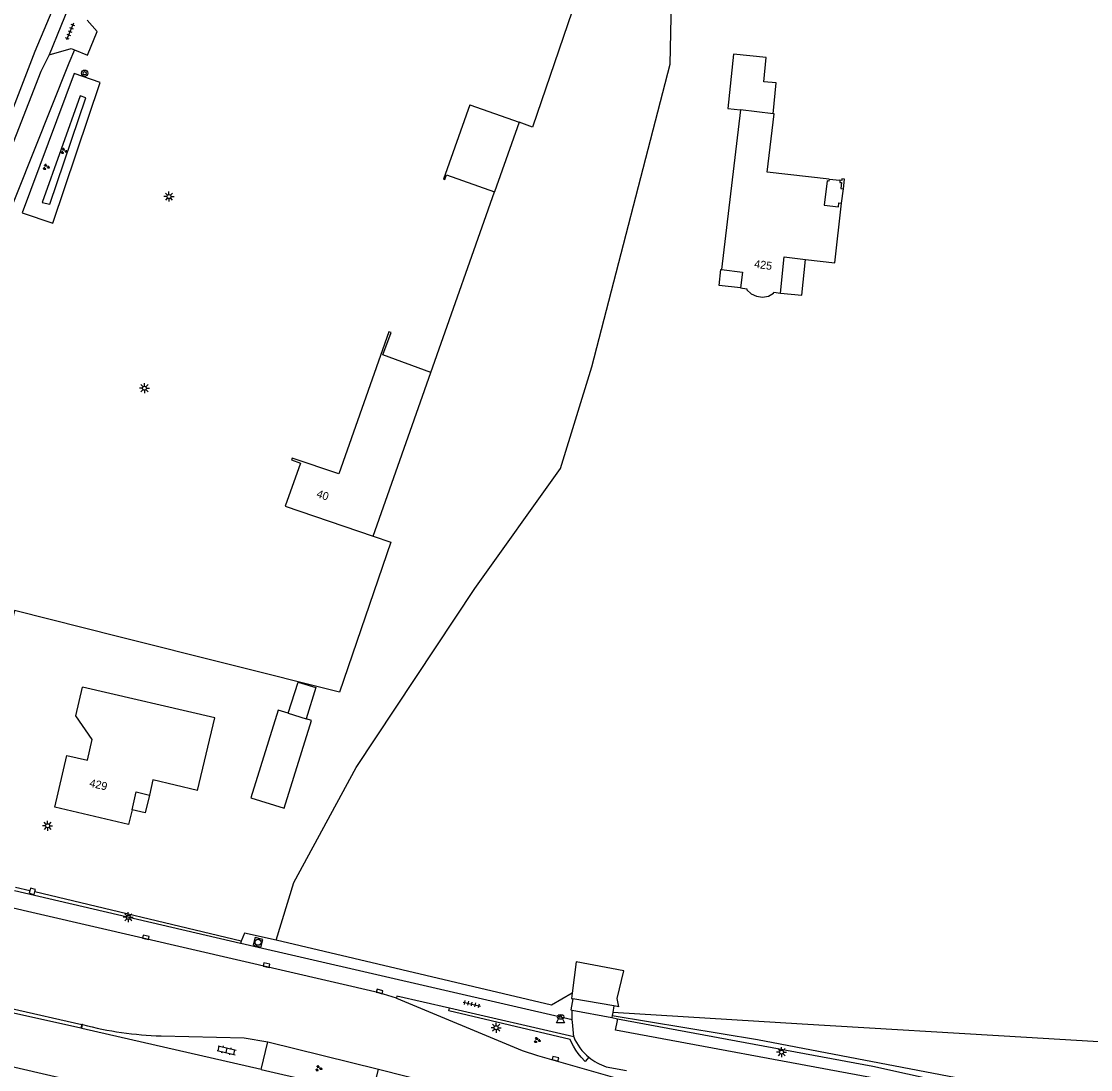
# Model space of a CAD drawing. Extents: x 128999 to 131010, y 395498 to 399007.
# Drawn here: x 130761.9 to 130895.4, y 396690 to 396821 of the extents above; entities that cross this region are included whole.
import ezdxf

# ---------------------------------------------------------------- set-up
doc = ezdxf.new("R2010")
doc.units = 0
for name, color, linetype in [('gg-afsc-hekwerk', 7, 'Continuous'), ('gg-afsc-muur', 7, 'Continuous'), ('gg-anno-huisnummerreeks BGT', 7, 'Continuous'), ('gg-bbg-bijgebouw', 7, 'Continuous'), ('gg-bbg-gedigitaliseerde bebouwing', 7, 'Continuous'), ('gg-bbg-gedigitaliseerde bijgebouw', 7, 'Continuous'), ('gg-bbg-hoofdgebouw', 7, 'Continuous'), ('gg-bbg-luifel en loopbrug', 7, 'Continuous'), ('gg-bbg-onder overbouw', 7, 'Continuous'), ('gg-bbg-pand overbouw', 7, 'Continuous'), ('gg-bbg-pilaar onder overbouw', 7, 'Continuous'), ('gg-bbg-pilaar pand', 7, 'Continuous'), ('gg-knt-BGT kruinlijn', 7, 'Continuous'), ('gg-knt-bovenkant onderkant talud', 7, 'Continuous'), ('gg-knt-verharding', 7, 'Continuous'), ('gg-knt-verharding nz', 7, 'Continuous'), ('gt-grn-groengrens', 7, 'Continuous'), ('gt-grn-weggrens', 7, 'Continuous'), ('gt-symb-boom', 7, 'Continuous'), ('gt-symb-brandkraan', 7, 'Continuous'), ('gt-symb-groenvak', 7, 'Continuous'), ('gt-symb-klinker verharding', 7, 'Continuous'), ('gt-symb-kolk', 7, 'Continuous'), ('gt-symb-lichtmast', 7, 'Continuous'), ('gt-symb-rioolschacht', 7, 'Continuous'), ('gt-symb-tegel verharding', 7, 'Continuous'), ('gt-symb-waterafsluiter', 7, 'Continuous')]:
    doc.layers.add(name, color=color, linetype=linetype)

# ---------------------------------------------------------------- blocks, each defined once
blk = doc.blocks.new('gt0-GRVAK')
at = {"layer": 'gt-symb-groenvak'}
for p, q in [((-0.11, 0.19), (-0.23, 0.24)), ((-0.18, 0.15), (0.09, 0.15)), ((-0.09, 0.21), (-0.16, 0.32)), ((-0.05, 0.21), (-0.05, 0.39)), ((0, 0.21), (0.06, 0.32)), ((0.01, 0.19), (0.13, 0.24)), ((0.26, -0.05), (0.2, 0.06)), ((0.31, -0.05), (0.31, 0.13)), ((0.35, -0.05), (0.41, 0.06)), ((-0.24, -0.23), (-0.36, -0.18)), ((-0.32, -0.26), (-0.05, -0.26)), ((-0.23, -0.21), (-0.29, -0.1)), ((-0.18, -0.2), (-0.18, -0.02)), ((-0.14, -0.21), (-0.07, -0.1)), ((-0.12, -0.23), (0, -0.18)), ((0.24, -0.07), (0.12, -0.02)), ((0.17, -0.11), (0.44, -0.11)), ((0.37, -0.07), (0.49, -0.02))]:
    blk.add_line(p, q, dxfattribs=at)
blk = doc.blocks.new('gt0-LMAST')
at = {"layer": 'gt-symb-lichtmast'}
for p, q in [((-0.18, 0.17), (-0.45, 0.44)), ((-0.01, 0.25), (-0.01, 0.62)), ((0.17, 0.17), (0.44, 0.44)), ((-0.26, 0), (-0.63, 0)), ((-0.18, -0.18), (-0.45, -0.45)), ((-0.01, -0.25), (-0.01, -0.63)), ((0.44, -0.45), (0.17, -0.18)), ((0.24, 0), (0.62, 0))]:
    blk.add_line(p, q, dxfattribs=at)
blk.add_circle((-0.01, 0), 0.25, dxfattribs=at)
blk = doc.blocks.new('gt0-KOLK')
at = {"layer": 'gt-symb-kolk'}
blk.add_lwpolyline([(0, 0), (0.38, 0), (0.38, 0.4), (-0.38, 0.4), (-0.38, 0), (0, 0)], dxfattribs=at)
blk = doc.blocks.new('gt0-RS')
at = {"layer": 'gt-symb-rioolschacht'}
blk.add_lwpolyline([(-0.5, -0.5), (0.5, -0.5), (0.5, 0.5), (-0.5, 0.5)], close=True, dxfattribs=at)
blk.add_circle((0, 0), 0.375, dxfattribs=at)
blk = doc.blocks.new('gt0-TEG1')
at = {"layer": 'gt-symb-tegel verharding'}
for p, q in [((-1.12, 0), (1.12, 0)), ((-0.9, -0.25), (-0.9, 0.25)), ((-0.45, -0.25), (-0.45, 0.25)), ((0, -0.25), (0, 0.25)), ((0.45, -0.25), (0.45, 0.25)), ((0.9, -0.25), (0.9, 0.25))]:
    blk.add_line(p, q, dxfattribs=at)
blk = doc.blocks.new('gt0-WAFSL')
at = {"layer": 'gt-symb-waterafsluiter'}
for p, q in [((-0.5, -0.33), (0, 0.67)), ((0, 0.67), (0.5, -0.33)), ((0.5, -0.33), (-0.5, -0.33))]:
    blk.add_line(p, q, dxfattribs=at)
blk = doc.blocks.new('gt0-BR')
at = {"layer": 'gt-symb-brandkraan'}
for centre, radius, start, end in [((-0.24, 0), 0.206, 107.5669, 252.4331), ((0.6, -2.66), 3, 106.892, 107.5669), ((0, -0.69), 0.938, 73.108, 106.892), ((-0.6, -2.66), 3, 72.4331, 73.108), ((0.24, 0), 0.206, 287.567, 72.4331), ((0.6, 2.66), 3, 252.4331, 253.108), ((0, 0.69), 0.938, 253.108, 286.8921), ((-0.6, 2.66), 3, 286.8921, 287.567)]:
    blk.add_arc(centre, radius, start, end, dxfattribs=at)
blk = doc.blocks.new('gt0-BOOM')
at = {"layer": 'gt-symb-boom'}
for radius in [0.4, 0.2]:
    blk.add_circle((0, 0), radius, dxfattribs=at)
blk = doc.blocks.new('gt0-KL1')
at = {"layer": 'gt-symb-klinker verharding'}
for p, q in [((-1.15, 0.3), (1.15, 0.3)), ((-1, -0.3), (-1, 0.3)), ((-0.5, 0.3), (-0.5, 0.45)), ((0, -0.3), (0, 0.3)), ((0.5, 0.3), (0.5, 0.45)), ((1, -0.3), (1, 0.3)), ((-1.15, -0.3), (1.15, -0.3)), ((-0.5, -0.45), (-0.5, -0.3)), ((0.5, -0.45), (0.5, -0.3))]:
    blk.add_line(p, q, dxfattribs=at)

msp = doc.modelspace()

# ---------------------------------------------------------------- linework, layer by layer
at = {"layer": 'gg-afsc-hekwerk'}
for p, q in [((130762.91, 396712.35), (130761.12, 396712.78)), ((130789.32, 396706.07), (130763.55, 396712.2))]:
    msp.add_line(p, q, dxfattribs=at)
for points in [[(130774.03, 396744.08), (130761, 396747.35), (130757.38, 396731.79)], [(130793.68, 396706.16), (130789.73, 396707.07), (130789.32, 396706.07)], [(130830.68, 396699.56), (130828.1, 396698.06), (130793.68, 396706.16)], [(130836.48, 396697.86), (130836.3, 396698.91), (130837.14, 396702.36), (130831.18, 396703.48), (130830.68, 396699.56)]]:
    msp.add_lwpolyline(points, dxfattribs=at)
at = {"layer": 'gg-afsc-muur'}
msp.add_line((130813.02, 396777.12), (130820.95, 396799.68), dxfattribs=at)
for points in [[(130762.91, 396712.35), (130762.84, 396712.04), (130763.48, 396711.89), (130763.55, 396712.2)], [(130763.55, 396712.2), (130763.62, 396712.52), (130762.99, 396712.66), (130762.91, 396712.35)]]:
    msp.add_lwpolyline(points, dxfattribs=at)
at = {"layer": 'gg-bbg-bijgebouw'}
msp.add_lwpolyline([(130817.88, 396810.55), (130814.61, 396801.25), (130814.74, 396801.2), (130814.95, 396801.79), (130820.95, 396799.68)], dxfattribs=at)
at = {"layer": 'gg-bbg-gedigitaliseerde bebouwing'}
for p, q in [((130805.82, 396756.65), (130813.02, 396777.12)), ((130794.83, 396760.41), (130805.82, 396756.65))]:
    msp.add_line(p, q, dxfattribs=at)
msp.add_lwpolyline([(130783.87, 396724.88), (130786.01, 396733.94), (130769.49, 396737.79)], dxfattribs=at)
at = {"layer": 'gg-bbg-gedigitaliseerde bijgebouw'}
for p, q in [((130817.88, 396810.55), (130824.04, 396808.36)), ((130824.04, 396808.36), (130820.95, 396799.68)), ((130795.2, 396734.53), (130797.44, 396733.83))]:
    msp.add_line(p, q, dxfattribs=at)
msp.add_lwpolyline([(130795.2, 396734.53), (130796.42, 396738.43), (130798.66, 396737.73), (130797.44, 396733.83)], dxfattribs=at)
at = {"layer": 'gg-bbg-hoofdgebouw'}
for p, q in [((130851.71, 396809.9), (130849.31, 396789.95)), ((130855.77, 396809.42), (130851.71, 396809.9))]:
    msp.add_line(p, q, dxfattribs=at)
for points in [[(130862.77, 396801.27), (130855.02, 396802.13), (130855.89, 396809.4), (130855.77, 396809.42)], [(130859.83, 396791.23), (130863.46, 396790.8), (130864.3, 396798.26)], [(130856.68, 396787.03), (130857.14, 396791.54), (130859.83, 396791.23)], [(130849.31, 396789.95), (130851.93, 396789.63), (130851.7, 396787.68)], [(130851.7, 396787.68), (130852.49, 396787.57), (130852.48, 396787.43), (130853.04, 396786.94), (130853.71, 396786.62), (130854.44, 396786.52), (130855.18, 396786.63), (130855.82, 396787.02), (130855.84, 396787.14), (130856.68, 396787.03)], [(130813.02, 396777.12), (130807.03, 396779.3), (130808.05, 396782.09), (130807.77, 396782.19), (130801.53, 396764.42), (130795.68, 396766.38), (130795.61, 396766.18), (130796.72, 396765.79), (130794.83, 396760.41)], [(130775.69, 396722.46), (130775.25, 396720.61), (130766.06, 396722.78), (130767.54, 396729.26), (130770.11, 396728.68), (130770.71, 396731.26), (130768.67, 396734.19), (130769.49, 396737.79)], [(130783.87, 396724.88), (130778.3, 396726.19), (130777.85, 396724.31)]]:
    msp.add_lwpolyline(points, dxfattribs=at)
at = {"layer": 'gg-bbg-luifel en loopbrug'}
for points in [[(130855.77, 396809.42), (130856.17, 396813.27), (130854.6, 396813.43), (130854.9, 396816.44), (130850.81, 396816.86), (130850.11, 396810.07), (130851.71, 396809.9)], [(130856.68, 396787.03), (130859.37, 396786.75), (130859.83, 396791.23)], [(130851.7, 396787.68), (130849.01, 396787.95), (130849.22, 396789.96), (130849.31, 396789.95)], [(130795.2, 396734.53), (130793.96, 396734.92), (130790.53, 396723.95), (130794.69, 396722.65), (130798.12, 396733.62), (130797.44, 396733.83)]]:
    msp.add_lwpolyline(points, dxfattribs=at)
at = {"layer": 'gg-bbg-onder overbouw'}
for points in [[(130862.77, 396801.27), (130862.74, 396801), (130862.52, 396801.03), (130862.16, 396798.02), (130863.93, 396797.81), (130863.99, 396798.3), (130864.3, 396798.26)], [(130775.69, 396722.46), (130776.22, 396724.7), (130777.85, 396724.31)]]:
    msp.add_lwpolyline(points, dxfattribs=at)
at = {"layer": 'gg-bbg-pand overbouw'}
for p, q in [((130862.77, 396801.27), (130864.12, 396801.12)), ((130864.3, 396798.26), (130864.54, 396800.05))]:
    msp.add_line(p, q, dxfattribs=at)
msp.add_lwpolyline([(130777.85, 396724.31), (130777.33, 396722.07), (130775.69, 396722.46)], dxfattribs=at)
at = {"layer": 'gg-bbg-pilaar onder overbouw'}
msp.add_lwpolyline([(130864.12, 396801.12), (130864.09, 396800.85), (130864.3, 396800.82), (130864.22, 396800.09), (130864.54, 396800.05)], dxfattribs=at)
at = {"layer": 'gg-bbg-pilaar pand'}
msp.add_lwpolyline([(130864.54, 396800.05), (130864.68, 396801.27), (130864.36, 396801.31), (130864.34, 396801.09), (130864.12, 396801.12)], dxfattribs=at)
at = {"layer": 'gg-knt-BGT kruinlijn'}
msp.add_lwpolyline([(130769.92, 396811.42), (130769.19, 396811.68), (130764.48, 396798.33), (130765.44, 396798.15), (130769.92, 396811.42)], dxfattribs=at)
at = {"layer": 'gg-knt-bovenkant onderkant talud'}
msp.add_lwpolyline([(130771.7, 396813.31), (130768.47, 396814.47), (130761.96, 396797.03), (130765.8, 396795.74), (130771.7, 396813.31)], dxfattribs=at)
at = {"layer": 'gg-knt-verharding'}
for p, q in [((130768.29, 396824.1), (130765.33, 396816.8)), ((130789.25, 396705.78), (130761.02, 396712.33)), ((130835.89, 396697.97), (130830.75, 396698.87)), ((130760.61, 396697.63), (130769.41, 396695.66)), ((130830.86, 396694.11), (130815.34, 396697.68)), ((130830.67, 396697.14), (130830.67, 396697.42)), ((130830.67, 396697.42), (130835.61, 396696.5)), ((130830.68, 396696.21), (130830.67, 396697.14)), ((130835.73, 396697.15), (130835.66, 396696.76)), ((130835.89, 396697.97), (130835.73, 396697.15)), ((130836.48, 396697.86), (130835.89, 396697.97)), ((130830.7, 396695.94), (130830.68, 396696.21)), ((130830.86, 396694.11), (130830.7, 396695.94)), ((130835.66, 396696.76), (130835.61, 396696.5)), ((130835.61, 396696.5), (130836.35, 396696.36)), ((130836.09, 396694.93), (130836.31, 396696.13)), ((130836.31, 396696.13), (130836.35, 396696.36)), ((130791.82, 396690.02), (130792.67, 396693.46)), ((130792.67, 396693.46), (130806.48, 396690.07)), ((130767.7, 396688.73), (130755.78, 396691.49)), ((130834.92, 396690.37), (130837.44, 396689.91)), ((130791.82, 396690.02), (130805.7, 396686.85)), ((130805.7, 396686.85), (130806.48, 396690.07))]:
    msp.add_line(p, q, dxfattribs=at)
for points in [[(130768.49, 396817.42), (130770.14, 396816.75), (130771.34, 396819.7), (130770.07, 396821.1)], [(130765.33, 396816.8), (130768.09, 396817.58), (130768.49, 396817.42)], [(130765.33, 396816.8), (130764.31, 396814.69), (130759.67, 396802.84), (130755.1, 396789.67), (130750.72, 396776.21), (130747, 396763.76), (130744.26, 396754.05), (130741.99, 396743.76), (130740.52, 396733.39)], [(130808.71, 396698.92), (130806.55, 396699.58), (130746.94, 396713.4)], [(130830.68, 396696.21), (130789.29, 396705.77), (130789.25, 396705.78)], [(130815.34, 396697.68), (130808.75, 396699.2), (130808.71, 396698.92)], [(130808.71, 396698.92), (130824.41, 396692.4), (130826.33, 396691.77), (130842.38, 396687.19)], [(130830.75, 396698.87), (130830.49, 396697.46), (130830.67, 396697.42)], [(130830.68, 396699.56), (130830.57, 396698.91), (130830.75, 396698.87)], [(130769.41, 396695.66), (130769.3, 396695.18), (130760.51, 396697.15), (130760.61, 396697.63)], [(130791.82, 396690.02), (130769.4, 396695.16), (130769.51, 396695.64)], [(130836.35, 396696.36), (130868.21, 396690.43), (130881.59, 396687.48), (130890.43, 396685.21), (130895.11, 396684.11)], [(130917.09, 396677.59), (130881.91, 396685.9), (130867.93, 396689.03), (130836.09, 396694.93)], [(130779.33, 396694.21), (130789.69, 396693.98), (130792.67, 396693.46)], [(130806.48, 396690.07), (130816.5, 396687.51), (130826.18, 396684.93), (130835.85, 396682.22), (130846.94, 396678.96)]]:
    msp.add_lwpolyline(points, dxfattribs=at)
for centre, radius, start, end in [((130780.61, 396737.67), 43.47, 255.2033, 268.3194), ((130836.94, 396696.64), 6.59, 202.5618, 230.3969), ((130837.06, 396696.87), 6.85, 230.8629, 251.806)]:
    msp.add_arc(centre, radius, start, end, dxfattribs=at)
at = {"layer": 'gg-knt-verharding nz'}
msp.add_lwpolyline([(130743.37, 396756.96), (130747.85, 396772.2), (130752.65, 396787.37), (130757.86, 396802.42), (130763.6, 396817.24), (130769.77, 396831.92), (130776.51, 396846.35), (130783.76, 396860.54), (130791.21, 396874.52), (130799.23, 396888.26), (130807.76, 396901.7), (130816.11, 396914.1), (130822.94, 396923.86), (130832.55, 396936.54), (130842.61, 396948.89), (130853.02, 396960.93), (130863.8, 396972.66)], dxfattribs=at)
at = {"layer": 'gt-grn-groengrens'}
msp.add_line((130789.32, 396706.07), (130789.25, 396705.78), dxfattribs=at)
for points in [[(130850.38, 396879.88), (130825.72, 396807.76), (130824.04, 396808.36)], [(130793.68, 396706.16), (130795.9, 396713.38), (130803.67, 396727.74), (130818.49, 396750.11), (130829.19, 396765.11), (130833.11, 396777.79), (130842.9, 396815.61), (130843.29, 396833.31), (130842.64, 396847.94), (130845.12, 396862.77), (130849.56, 396861.73), (130852.58, 396871.01)], [(130768.49, 396817.42), (130767.78, 396815.75), (130759.11, 396794), (130752.98, 396775.48), (130748.25, 396759.2), (130749.35, 396758.94)], [(130805.82, 396756.65), (130808, 396755.9), (130801.59, 396737.16), (130774.03, 396744.08)], [(130832.74, 396691.56), (130832.28, 396691.01), (130831.79, 396691.56), (130831.43, 396692.02), (130831.14, 396692.44), (130830.84, 396692.93), (130830.58, 396693.4), (130830.4, 396693.78), (130815.26, 396697.34), (130815.34, 396697.68)], [(130897.84, 396693.38), (130887.44, 396694.02), (130859.41, 396695.7), (130835.73, 396697.15)], [(130835.66, 396696.76), (130853.83, 396693.76), (130884.3, 396687.93), (130895.42, 396685.18)]]:
    msp.add_lwpolyline(points, dxfattribs=at)
at = {"layer": 'gt-grn-weggrens'}
msp.add_line((130769.51, 396695.64), (130769.41, 396695.66), dxfattribs=at)

# ---------------------------------------------------------------- block references
at = {"layer": 'gt-symb-boom'}
msp.add_blockref('gt0-BOOM', (130769.77, 396814.49), dxfattribs=at)
at = {"layer": 'gt-symb-brandkraan'}
msp.add_blockref('gt0-BR', (130829.23, 396696.59), dxfattribs=at)
at = {"layer": 'gt-symb-groenvak'}
for p in [(130767.18, 396804.76), (130764.95, 396802.77), (130826.28, 396693.68), (130798.99, 396690.16)]:
    msp.add_blockref('gt0-GRVAK', p, dxfattribs=at)
at = {"layer": 'gt-symb-klinker verharding', "rotation": -12.882979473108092}
msp.add_blockref('gt0-KL1', (130787.5, 396692.42), dxfattribs=at)
at = {"layer": 'gt-symb-kolk'}
for p, rotation in [((130777.37, 396706.33), -13.11914463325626), ((130792.44, 396702.86), -13.299584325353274), ((130806.55, 396699.58), -15.30032444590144), ((130828.52, 396691.18), -15.00891367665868)]:
    msp.add_blockref('gt0-KOLK', p, dxfattribs=dict(at, rotation=rotation))
at = {"layer": 'gt-symb-lichtmast'}
for p in [(130780.31, 396799.08), (130777.25, 396775.14), (130765.15, 396720.47), (130775.22, 396709.04), (130821.18, 396695.24), (130856.83, 396692.19)]:
    msp.add_blockref('gt0-LMAST', p, dxfattribs=at)
at = {"layer": 'gt-symb-rioolschacht', "rotation": -14.24474247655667}
msp.add_blockref('gt0-RS', (130791.43, 396705.92), dxfattribs=at)
at = {"layer": 'gt-symb-tegel verharding'}
for p, rotation in [((130767.93, 396819.7), -112.7697266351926), ((130818.14, 396698.2), -12.938810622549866)]:
    msp.add_blockref('gt0-TEG1', p, dxfattribs=dict(at, rotation=rotation))
at = {"layer": 'gt-symb-waterafsluiter'}
msp.add_blockref('gt0-WAFSL', (130829.2, 396696.19), dxfattribs=at)

# ---------------------------------------------------------------- texts
at = {"layer": 'gg-anno-huisnummerreeks BGT'}
for s, rotation, p in [('425', 351.9, (130853.36, 396790.21)), ('40', 340.7, (130798.65, 396761.56)), ('429', 346.7, (130770.29, 396725.38))]:
    msp.add_text(s, height=1, rotation=rotation, dxfattribs=at).set_placement(p)

doc.saveas('drawing.dxf')
